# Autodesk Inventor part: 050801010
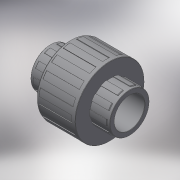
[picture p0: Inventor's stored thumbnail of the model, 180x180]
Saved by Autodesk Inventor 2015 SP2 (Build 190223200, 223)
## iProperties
Created: 2017-10
Part Number: 050801010
Material: Generic
Description: PLASSON THR.UNION+O RING PVC 1"
Document SubType Name: Modeling
Designer: KIM
Density: 1 g/cm^3
Appearance: Default
Author: KIM
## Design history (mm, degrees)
derived "050801.ipt"
feature "Solid1::050801.ipt"
tag "TaggingFeature1"
body "Solid1"
other parameters: "d0" = 57, "d3" = 30.291, "d4" = 30.291, "d5" = 40.58994, "d6" = 39.37224, "d7" = 40.58994, "d8" = 59, "d11" = 27.2619, "d14" = 15, "d17" = 2, "d19" = 57.82, "d20" = 2, "d21" = 0.885, "d25" = 5.9, "d26" = 2.95, "d27" = 22.5, "d28" = 0, "d32" = 5.9, "d33" = 2.95, "d35" = 0, "d39" = 0.16, "d45" = 0.60885, "d49" = 360 deg, "d51" = 0.59, "d55" = 360 deg, "d58" = 15, "d_" = 16, "E_" = 59, "H_" = 57, "l_" = 14, "Z_" = 11, "G_" = 30.291, "d24" = 25, "d40" = 0.60885, "d44" = 0.59
